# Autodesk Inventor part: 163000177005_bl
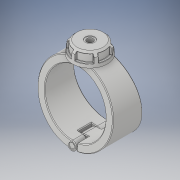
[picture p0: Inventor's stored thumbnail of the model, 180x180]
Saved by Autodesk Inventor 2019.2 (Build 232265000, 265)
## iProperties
Created: 2022-02
Part Number: 163000177005_bl
Material: Generic
Description: Plassadle Threaded 177x1/2''
Document SubType Name: Modeling
Designer: comp2
Density: 1 g/cm^3
Appearance: Default
Author: comp2
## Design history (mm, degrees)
derived "16300.ipt"
feature "Solid1::16300.ipt" dims "ScaleForDerivedMember" = 10
feature "Solid2::16300.ipt" dims "ScaleForDerivedMember" = 10
feature "Solid3::16300.ipt" dims "ScaleForDerivedMember" = 10
feature "Solid4::16300.ipt" dims "ScaleForDerivedMember" = 10
tag "TaggingFeature1"
body "Solid1"
body "Solid2"
body "Solid3"
body "Solid4"
other parameters: "d" = 177 [user parameter], "d1" = 25 [user parameter], "E_" = 54 [user parameter], "E1" = 102 [user parameter], "H1" = 255 [user parameter], "H2" = 52 [user parameter], "H3" = 78 [user parameter], "H_costum" = 49 [user parameter], "Rp" = 18.631 [user parameter], "d128" = 36.1 [user parameter], "d0" = 177 [user parameter], "d3" = 88.5 [user parameter], "d7" = 209 [user parameter], "d8" = 85 deg [user parameter], "d9" = 45 deg [user parameter], "d10" = 102 [user parameter], "d11" = 49 [user parameter], "d12" = 25.27 [user parameter], "d13" = 42.84 [user parameter], "d14" = 27.9465 [user parameter], "d42" = 4.3 [user parameter], "d49" = 4.4 [user parameter], "d51" = 0 [user parameter], "d52" = 30.1 [user parameter], "d53" = 121 [user parameter], "d54" = 38.5 [user parameter], "d55" = 0 [user parameter], "d56" = 22 [user parameter], "d57" = 22 [user parameter], "d59" = 0 [user parameter], "d61" = 0 [user parameter], "d62" = 38.5 [user parameter], "d63" = 0 [user parameter], "d65" = 0 [user parameter], "d67" = 0 [user parameter], "d69" = 0 [user parameter], "d70" = 1 [user parameter], "d71" = 105.6 [user parameter], "d72" = 0 [user parameter], "d73" = 2 [user parameter], "d78" = 86.7 [user parameter], "d79" = 5.1 [user parameter], "d80" = 60 deg [user parameter], "d81" = 5.1 [user parameter], "d84" = 0 [user parameter], "d85" = 1 [user parameter], "d87" = 360 deg [user parameter], "d122" = 52 [user parameter], "d124" = 42.80128 [user parameter], "d125" = 1.805 [user parameter], "d127" = 255 [user parameter], "d129" = 18.631 [user parameter], "d130" = 15.83635 [user parameter], "d131" = 33.8 [user parameter], "d132" = 45 deg [user parameter], "d133" = 23.66 [user parameter], "d134" = 9.3155 [user parameter], "d136" = 0 [user parameter], "d138" = 0 [user parameter]
